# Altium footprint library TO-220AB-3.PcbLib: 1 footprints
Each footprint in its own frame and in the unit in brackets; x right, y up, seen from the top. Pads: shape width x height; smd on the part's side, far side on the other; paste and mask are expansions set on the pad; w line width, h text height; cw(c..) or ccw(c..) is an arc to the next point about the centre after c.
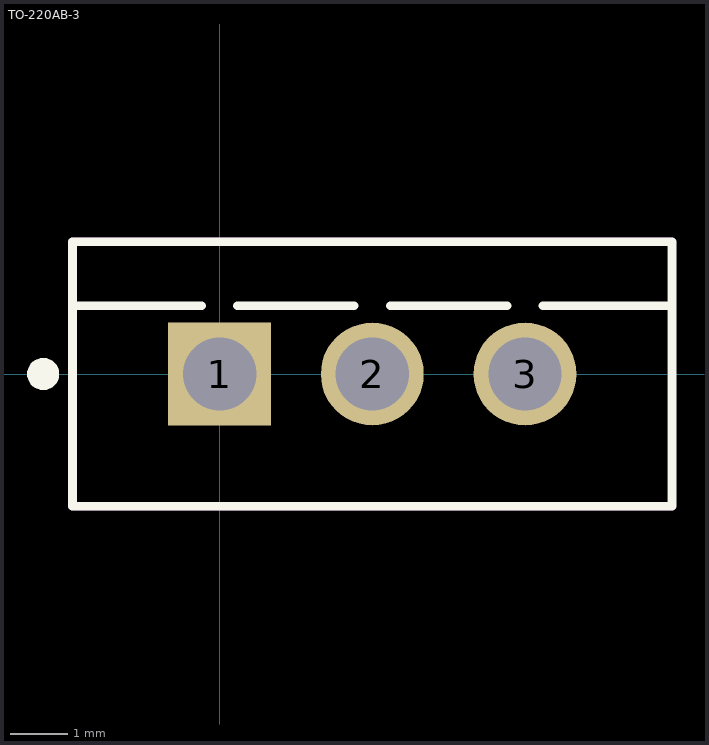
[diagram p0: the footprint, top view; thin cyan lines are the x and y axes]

## TO-220AB-3 [mil]
pads (3):
  rect 70x70 hole 50: 1(0,0)
  round 70 hole 50: 2(103.94,0) 3(207.87,0)
Top Overlay:
  circle w11.81: c-120,0 r5
  lines w6: -99.19,46.5 -12.3,46.5 ; 12.3,46.5 91.63,46.5 ; 116.24,46.5 195.57,46.5 ; 220.18,46.5 307.08,46.5 ; -100,-90 308.03,-90 308.03,90 -100,90 -100,-90
Mechanical 15:
  lines w6: -100,-90 -100,90 307.56,90 307.56,-90 -100,-90
3D body "TO220AB_VIS.step": height 600, standoff -260, extent -103.07,-91.5 310.94,91.5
